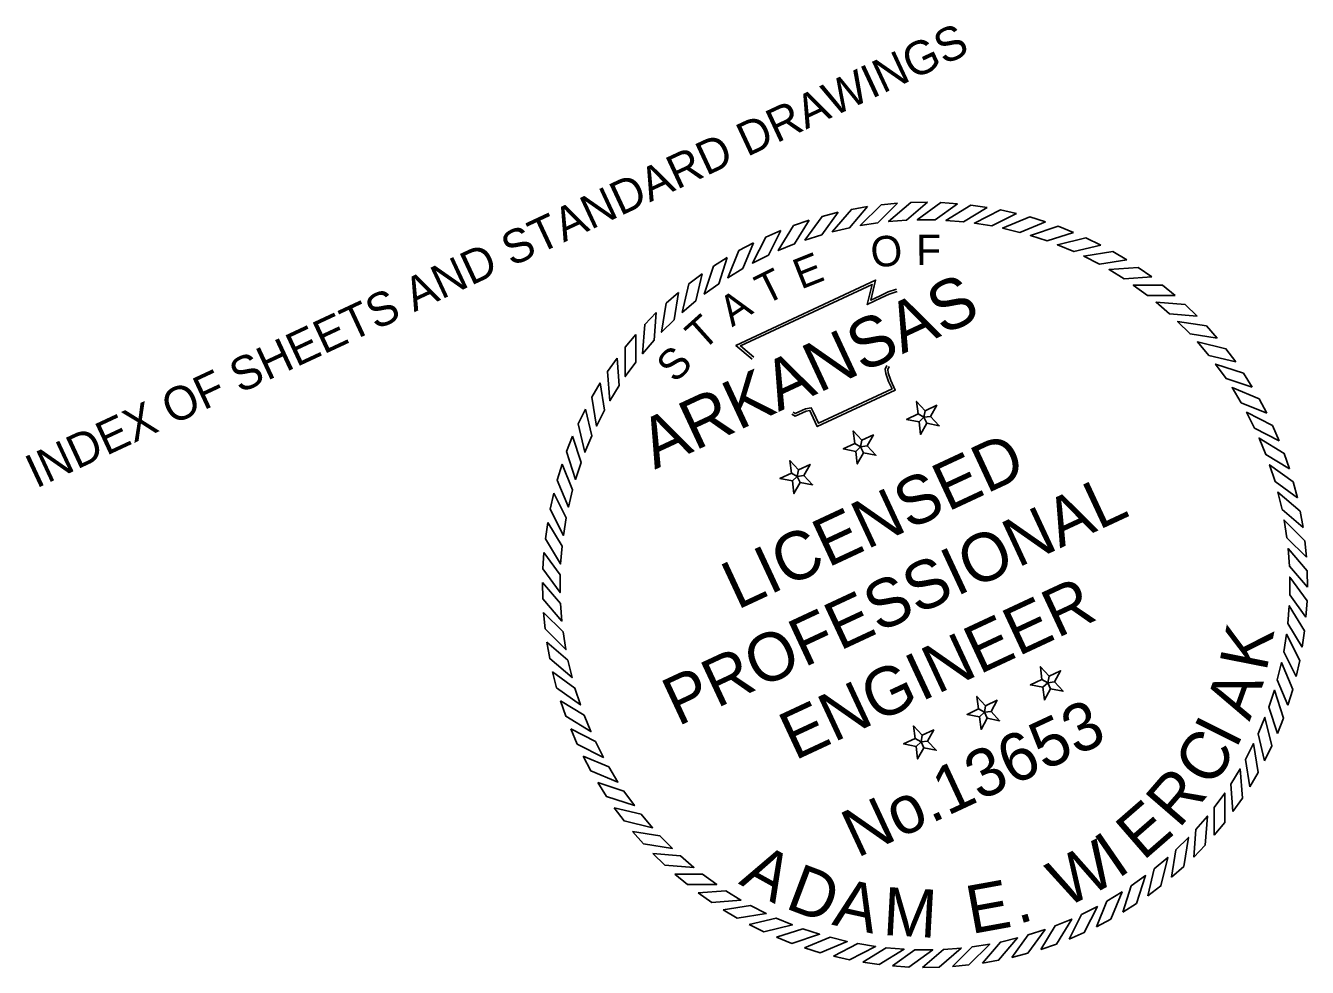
# Model space of a CAD drawing. Extents: x 757022 to 766943, y 1656388 to 1662319.
# Drawn here: x 758854.8 to 759257, y 1658713.1 to 1659008.6 of the extents above; entities that cross this region are included whole.
import ezdxf

# ---------------------------------------------------------------- set-up
doc = ezdxf.new("R2010")
doc.units = 0
for name, color, linetype in [('1', 7, 'Continuous'), ('G-ANNO-STMP-AEW', 7, 'Continuous'), ('G-ANNO-TEXT', 7, 'Continuous')]:
    doc.layers.add(name, color=color, linetype=linetype)

msp = doc.modelspace()

# ---------------------------------------------------------------- linework, layer by layer
at = {"layer": 'G-ANNO-STMP-AEW'}
for points in [[(759118.97, 1658951.77), (759113.89, 1658950.88), (759107.91, 1658943.89), (759113.34, 1658945.17)], [(759128.34, 1658952.82), (759123.2, 1658952.33), (759116.69, 1658945.83), (759122.2, 1658946.68)], [(759137.75, 1658953.13), (759132.59, 1658953.05), (759125.6, 1658947.07), (759131.16, 1658947.49)], [(759147.17, 1658952.7), (759142.02, 1658953.02), (759134.58, 1658947.62), (759140.15, 1658947.6)], [(759156.52, 1658951.53), (759151.41, 1658952.26), (759143.57, 1658947.45), (759149.12, 1658947)], [(759165.75, 1658949.63), (759160.71, 1658950.76), (759152.52, 1658946.59), (759158.02, 1658945.7)], [(759100.63, 1658947.49), (759095.75, 1658945.82), (759090.94, 1658937.98), (759096.1, 1658940.09)], [(759109.72, 1658949.99), (759104.72, 1658948.71), (759099.31, 1658941.27), (759104.62, 1658942.97)], [(759174.8, 1658947.02), (759169.87, 1658948.54), (759161.37, 1658945.02), (759166.79, 1658943.7)], [(759091.77, 1658944.28), (759087.04, 1658942.23), (759082.86, 1658934.04), (759087.84, 1658936.55)], [(759183.62, 1658943.7), (759178.82, 1658945.6), (759170.08, 1658942.76), (759175.37, 1658941.02)], [(759083.19, 1658940.39), (759078.63, 1658937.98), (759075.11, 1658929.48), (759079.87, 1658932.38)], [(759192.15, 1658939.7), (759187.52, 1658941.98), (759178.58, 1658939.83), (759183.72, 1658937.68)], [(759074.94, 1658935.84), (759070.58, 1658933.08), (759067.74, 1658924.33), (759072.26, 1658927.59)], [(759200.35, 1658935.05), (759195.91, 1658937.68), (759186.82, 1658936.24), (759191.78, 1658933.69)], [(759067.07, 1658930.65), (759062.94, 1658927.56), (759060.8, 1658918.61), (759065.05, 1658922.22)], [(759208.15, 1658929.76), (759203.93, 1658932.73), (759194.76, 1658932.01), (759199.5, 1658929.08)], [(759215.51, 1658923.88), (759211.54, 1658927.17), (759202.34, 1658927.17), (759206.84, 1658923.88)], [(759059.64, 1658924.87), (759055.76, 1658921.46), (759054.32, 1658912.37), (759058.28, 1658916.3)], [(759052.68, 1658918.51), (759049.08, 1658914.81), (759048.36, 1658905.64), (759052, 1658909.87)], [(759222.39, 1658917.44), (759218.69, 1658921.03), (759209.52, 1658921.76), (759213.74, 1658918.12)], [(759228.74, 1658910.48), (759225.33, 1658914.35), (759216.25, 1658915.79), (759220.18, 1658911.84)], [(759046.24, 1658911.64), (759042.94, 1658907.66), (759042.94, 1658898.46), (759046.24, 1658902.96)], [(759234.53, 1658903.04), (759231.43, 1658907.17), (759222.49, 1658909.32), (759226.1, 1658905.07)], [(759040.36, 1658904.27), (759037.39, 1658900.05), (759038.11, 1658890.88), (759041.04, 1658895.63)], [(759239.71, 1658895.18), (759236.95, 1658899.54), (759228.2, 1658902.38), (759231.47, 1658897.86)], [(759035.07, 1658896.47), (759032.44, 1658892.03), (759033.88, 1658882.95), (759036.43, 1658887.9)], [(759244.27, 1658886.93), (759241.85, 1658891.49), (759233.36, 1658895.01), (759236.25, 1658890.25)], [(759136.69, 1658885.71), (759137.09, 1658887.76), (759134.37, 1658890.68), (759134.86, 1658886.72)], [(759030.42, 1658888.28), (759028.14, 1658883.65), (759030.29, 1658874.7), (759032.44, 1658879.85)], [(759136.69, 1658885.71), (759134.86, 1658886.72), (759131.24, 1658885.04), (759135.16, 1658884.28)], [(759136.69, 1658885.71), (759138.77, 1658885.96), (759140.7, 1658889.45), (759137.09, 1658887.76)], [(759136.69, 1658885.71), (759137.57, 1658883.81), (759141.49, 1658883.05), (759138.77, 1658885.96)], [(759248.16, 1658878.34), (759246.11, 1658883.08), (759237.91, 1658887.26), (759240.43, 1658882.28)], [(759136.69, 1658885.71), (759135.16, 1658884.28), (759135.64, 1658880.32), (759137.57, 1658883.81)], [(759026.42, 1658879.75), (759024.51, 1658874.95), (759027.36, 1658866.2), (759029.1, 1658871.5)], [(759116.8, 1658876.43), (759117.2, 1658878.49), (759114.48, 1658881.4), (759114.97, 1658877.45)], [(759116.8, 1658876.43), (759118.88, 1658876.69), (759120.81, 1658880.17), (759117.2, 1658878.49)], [(759251.36, 1658869.48), (759249.69, 1658874.37), (759241.85, 1658879.17), (759243.97, 1658874.01)], [(759116.8, 1658876.43), (759114.97, 1658877.45), (759111.36, 1658875.76), (759115.27, 1658875)], [(759116.8, 1658876.43), (759115.27, 1658875), (759115.75, 1658871.05), (759117.69, 1658874.53)], [(759116.8, 1658876.43), (759117.69, 1658874.53), (759121.6, 1658873.77), (759118.88, 1658876.69)], [(759023.1, 1658870.93), (759021.58, 1658865.99), (759025.1, 1658857.5), (759026.42, 1658862.91)], [(759096.91, 1658867.16), (759097.31, 1658869.21), (759094.59, 1658872.13), (759095.08, 1658868.17)], [(759096.91, 1658867.16), (759098.99, 1658867.41), (759100.92, 1658870.9), (759097.31, 1658869.21)], [(759253.86, 1658860.4), (759252.58, 1658865.4), (759245.14, 1658870.8), (759246.85, 1658865.5)], [(759096.91, 1658867.16), (759095.08, 1658868.17), (759091.47, 1658866.49), (759095.38, 1658865.73)], [(759096.91, 1658867.16), (759095.38, 1658865.73), (759095.87, 1658861.77), (759097.8, 1658865.26)], [(759096.91, 1658867.16), (759097.8, 1658865.26), (759101.71, 1658864.5), (759098.99, 1658867.41)], [(759020.48, 1658861.87), (759019.36, 1658856.84), (759023.53, 1658848.64), (759024.42, 1658854.15)], [(759255.64, 1658851.14), (759254.76, 1658856.23), (759247.76, 1658862.2), (759249.05, 1658856.78)], [(759018.59, 1658852.64), (759017.86, 1658847.53), (759022.66, 1658839.69), (759023.12, 1658845.25)], [(759256.69, 1658841.78), (759256.21, 1658846.92), (759249.7, 1658853.42), (759250.56, 1658847.91)], [(759017.42, 1658843.29), (759017.09, 1658838.14), (759022.5, 1658830.7), (759022.52, 1658836.28)], [(759257, 1658832.36), (759256.92, 1658837.52), (759250.95, 1658844.52), (759251.37, 1658838.96)], [(759016.99, 1658833.88), (759017.07, 1658828.72), (759023.04, 1658821.73), (759022.62, 1658827.29)], [(759256.57, 1658822.95), (759256.9, 1658828.1), (759251.49, 1658835.54), (759251.47, 1658829.97)], [(759255.41, 1658813.6), (759256.14, 1658818.71), (759251.33, 1658826.55), (759250.87, 1658820.99)], [(759017.3, 1658824.46), (759017.78, 1658819.32), (759024.29, 1658812.82), (759023.43, 1658818.33)], [(759253.51, 1658804.37), (759254.64, 1658809.4), (759250.46, 1658817.6), (759249.57, 1658812.1)], [(759018.35, 1658815.1), (759019.23, 1658810.01), (759026.23, 1658804.04), (759024.94, 1658809.47)], [(759020.13, 1658805.84), (759021.41, 1658800.85), (759028.85, 1658795.44), (759027.15, 1658800.75)], [(759175.52, 1658802.42), (759175.92, 1658804.48), (759173.21, 1658807.4), (759173.69, 1658803.44)], [(759175.52, 1658802.42), (759177.6, 1658802.68), (759179.54, 1658806.16), (759175.92, 1658804.48)], [(759250.89, 1658795.32), (759252.41, 1658800.25), (759248.89, 1658808.75), (759247.57, 1658803.33)], [(759175.52, 1658802.42), (759173.69, 1658803.44), (759170.08, 1658801.75), (759173.99, 1658800.99)], [(759175.52, 1658802.42), (759173.99, 1658800.99), (759174.48, 1658797.04), (759176.41, 1658800.52)], [(759175.52, 1658802.42), (759176.41, 1658800.52), (759180.32, 1658799.76), (759177.6, 1658802.68)], [(759155.64, 1658793.15), (759156.04, 1658795.21), (759153.32, 1658798.12), (759153.8, 1658794.17)], [(759247.58, 1658786.5), (759249.48, 1658791.29), (759246.64, 1658800.04), (759244.9, 1658794.74)], [(759022.63, 1658796.76), (759024.3, 1658791.88), (759032.14, 1658787.07), (759030.02, 1658792.23)], [(759155.64, 1658793.15), (759153.8, 1658794.17), (759150.19, 1658792.48), (759154.1, 1658791.72)], [(759155.64, 1658793.15), (759157.72, 1658793.4), (759159.65, 1658796.89), (759156.04, 1658795.21)], [(759155.64, 1658793.15), (759156.52, 1658791.25), (759160.43, 1658790.49), (759157.72, 1658793.4)], [(759155.64, 1658793.15), (759154.1, 1658791.72), (759154.59, 1658787.76), (759156.52, 1658791.25)], [(759243.58, 1658777.96), (759245.85, 1658782.6), (759243.7, 1658791.54), (759241.55, 1658786.4)], [(759025.84, 1658787.9), (759027.88, 1658783.16), (759036.08, 1658778.99), (759033.56, 1658783.96)], [(759135.75, 1658783.88), (759136.15, 1658785.93), (759133.43, 1658788.85), (759133.91, 1658784.89)], [(759135.75, 1658783.88), (759137.83, 1658784.13), (759139.76, 1658787.62), (759136.15, 1658785.93)], [(759135.75, 1658783.88), (759133.91, 1658784.89), (759130.3, 1658783.21), (759134.21, 1658782.45)], [(759135.75, 1658783.88), (759134.21, 1658782.45), (759134.7, 1658778.49), (759136.63, 1658781.98)], [(759135.75, 1658783.88), (759136.63, 1658781.98), (759140.55, 1658781.22), (759137.83, 1658784.13)], [(759238.92, 1658769.77), (759241.55, 1658774.21), (759240.11, 1658783.3), (759237.56, 1658778.34)], [(759029.73, 1658779.32), (759032.14, 1658774.75), (759040.64, 1658771.23), (759037.74, 1658776)], [(759233.64, 1658761.97), (759236.61, 1658766.19), (759235.88, 1658775.36), (759232.96, 1658770.62)], [(759034.28, 1658771.07), (759037.04, 1658766.71), (759045.79, 1658763.86), (759042.53, 1658768.39)], [(759227.76, 1658754.61), (759231.05, 1658758.58), (759231.05, 1658767.78), (759227.76, 1658763.28)], [(759039.46, 1658763.2), (759042.56, 1658759.07), (759051.5, 1658756.92), (759047.9, 1658761.17)], [(759221.32, 1658747.73), (759224.91, 1658751.43), (759225.63, 1658760.6), (759222, 1658756.37)], [(759045.25, 1658755.76), (759048.66, 1658751.89), (759057.75, 1658750.45), (759053.82, 1658754.4)], [(759214.36, 1658741.38), (759218.23, 1658744.79), (759219.67, 1658753.87), (759215.71, 1658749.94)], [(759051.6, 1658748.8), (759055.31, 1658745.21), (759064.48, 1658744.49), (759060.25, 1658748.12)], [(759206.92, 1658735.59), (759211.05, 1658738.69), (759213.2, 1658747.63), (759208.94, 1658744.02)], [(759058.48, 1658742.36), (759062.46, 1658739.07), (759071.65, 1658739.07), (759067.15, 1658742.36)], [(759199.05, 1658730.4), (759203.41, 1658733.17), (759206.25, 1658741.91), (759201.73, 1658738.65)], [(759065.85, 1658736.48), (759070.07, 1658733.51), (759079.24, 1658734.23), (759074.49, 1658737.16)], [(759190.8, 1658725.85), (759195.36, 1658728.26), (759198.88, 1658736.76), (759194.12, 1658733.86)], [(759073.65, 1658731.2), (759078.09, 1658728.57), (759087.17, 1658730.01), (759082.21, 1658732.55)], [(759182.22, 1658721.96), (759186.96, 1658724.01), (759191.13, 1658732.2), (759186.16, 1658729.69)], [(759081.84, 1658726.54), (759086.47, 1658724.27), (759095.42, 1658726.41), (759090.27, 1658728.56)], [(759090.37, 1658722.54), (759095.17, 1658720.64), (759103.92, 1658723.48), (759098.62, 1658725.22)], [(759164.27, 1658716.25), (759169.27, 1658717.54), (759174.68, 1658724.98), (759169.37, 1658723.27)], [(759173.36, 1658718.76), (759178.24, 1658720.42), (759183.05, 1658728.27), (759177.89, 1658726.15)], [(759099.19, 1658719.22), (759104.12, 1658717.7), (759112.62, 1658721.22), (759107.2, 1658722.54)], [(759155.02, 1658714.47), (759160.1, 1658715.36), (759166.08, 1658722.35), (759160.65, 1658721.07)], [(759108.24, 1658716.61), (759113.28, 1658715.48), (759121.48, 1658719.66), (759115.97, 1658720.55)], [(759117.47, 1658714.71), (759122.58, 1658713.98), (759130.43, 1658718.79), (759124.87, 1658719.24)], [(759126.82, 1658713.55), (759131.97, 1658713.22), (759139.42, 1658718.63), (759133.84, 1658718.64)], [(759136.24, 1658713.12), (759141.4, 1658713.19), (759148.39, 1658719.17), (759142.83, 1658718.75)], [(759145.66, 1658713.43), (759150.79, 1658713.91), (759157.3, 1658720.41), (759151.79, 1658719.56)]]:
    msp.add_lwpolyline(points, close=True, dxfattribs=at)
for points in [[(759082.76, 1658903.94), (759077.67, 1658908.24), (759121.52, 1658928.73), (759120.01, 1658922.41), (759122.97, 1658923.84), (759125.44, 1658925.03), (759128.06, 1658925.92)], [(759083.26, 1658904.52), (759079.08, 1658908.06), (759120.41, 1658927.36), (759118.88, 1658921.02), (759123.3, 1658923.15), (759125.73, 1658924.32), (759128.3, 1658925.2)], [(759125.76, 1658901.6), (759125.29, 1658900.64), (759125.47, 1658899.62), (759126.28, 1658897.23), (759127.69, 1658894.2), (759103.2, 1658882.78), (759101.3, 1658886.87), (759100.87, 1658887.78), (759099.74, 1658887.62), (759096.25, 1658886), (759095.19, 1658886.65)], [(759125.07, 1658901.94), (759124.49, 1658900.76), (759124.72, 1658899.43), (759125.57, 1658896.94), (759126.67, 1658894.57), (759103.58, 1658883.8), (759101.99, 1658887.19), (759101.33, 1658888.62), (759099.52, 1658888.36), (759096.3, 1658886.87), (759095.6, 1658887.3)]]:
    msp.add_lwpolyline(points, dxfattribs=at)

# ---------------------------------------------------------------- texts
at = {"layer": '1'}
msp.add_text('INDEX OF SHEETS AND STANDARD DRAWINGS', height=10.5516, rotation=25, dxfattribs=at).set_placement((758858.04, 1658863.27))
at = {"layer": 'G-ANNO-TEXT'}
for s, height, rotation, p in [('O', 9.55, 6.2218, (759120.46, 1658932.54)), ('F', 9.55, 0.3628, (759134.25, 1658933.42)), ('E', 9.55, 21.672, (759098.07, 1658925.71)), ('T', 9.55, 26.4789, (759086.87, 1658920.81)), ('ARKANSAS', 15.584, 25, (759052.2, 1658869.22)), ('A', 9.55, 33.6788, (759076.5, 1658913.87)), ('T', 9.55, 41.9015, (759067.27, 1658906.23)), ('S', 9.55, 44.7726, (759058.57, 1658896.16)), ('LICENSED', 15.087, 25, (759078.08, 1658825.17)), ('PROFESSIONAL', 15.0867, 25, (759059.45, 1658788.64)), ('ENGINEER', 15.087, 25, (759096.15, 1658777.91)), ('K', 15.09, 78.8471, (759244.12, 1658805.6)), ('A', 15.09, 70.185, (759238.86, 1658790.09)), ('No.13653', 15.027, 25, (759115.67, 1658747.33)), ('I', 15.09, 63.4057, (759234.55, 1658781.32)), ('C', 15.09, 57.1396, (759227.06, 1658769.04)), ('R', 15.09, 49.1616, (759216.65, 1658756.41)), ('E', 15.09, 41.0125, (759205.47, 1658746.33)), ('W', 15.09, 27.1127, (759180.85, 1658731.52)), ('I', 15.09, 34.5753, (759197.48, 1658740.7)), ('A', 15.09, 330.982, (759078.23, 1658739.45)), ('D', 15.09, 339.3022, (759092.71, 1658731.81)), ('A', 15.09, 347.6223, (759107.52, 1658726.54)), ('M', 15.09, 356.7969, (759123.57, 1658723.28)), ('E', 15.09, 10.2782, (759151.5, 1658723.53)), ('.', 15.09, 15.8583, (759166.22, 1658726.63))]:
    msp.add_text(s, height=height, rotation=rotation, dxfattribs=at).set_placement(p)

doc.saveas('drawing.dxf')
